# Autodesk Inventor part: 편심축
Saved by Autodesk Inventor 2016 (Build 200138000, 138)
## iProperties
Created: 2024-08
Part Number: 편심축
Material: 일반
Document SubType Name: Modeling
Designer: pc-2
Density: 1 g/cm^3
Appearance: 기본값
Author: jhkim
Sending System: Autodesk Inventor 2025
Preprocessor: ST-DEVELOPER v20
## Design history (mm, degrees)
node "편심축1"
node "솔리드2"
node "솔리드1"
